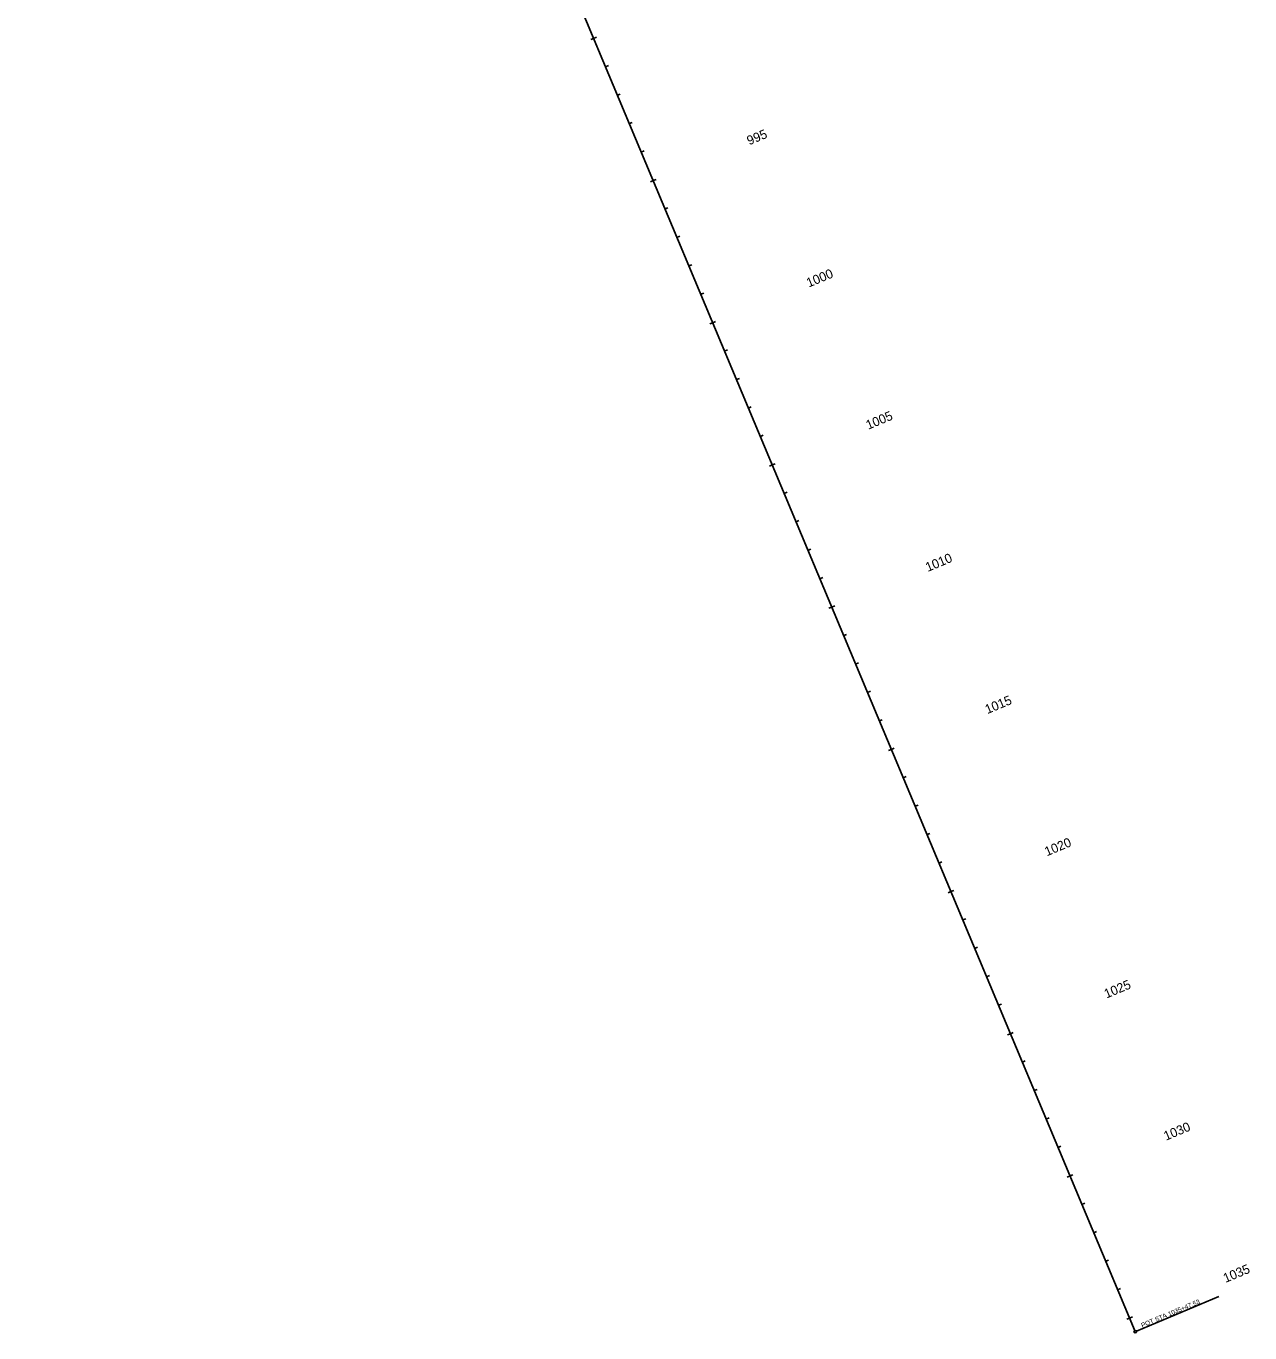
# Model space of a CAD drawing. Extents: x 2819977 to 2827606, y 116785 to 150320.
# Drawn here: x 2821726 to 2825694, y 116785 to 121023 of the extents above; entities that cross this region are included whole.
import ezdxf

# ---------------------------------------------------------------- set-up
doc = ezdxf.new("R2010")
doc.units = 0
doc.layers.add('Modeling-Flow Arrows-Existing', color=7, linetype='Continuous')
doc.layers.add('Modeling-Spot-Existing', color=7, linetype='Continuous')

msp = doc.modelspace()

# ---------------------------------------------------------------- linework, layer by layer
at = {"layer": 'Modeling-Flow Arrows-Existing'}
for p, q in [((2821725.8, 125379.3), (2825322, 116789)), ((2823565.9, 120983.8), (2823556.7, 120979.9)), ((2823565.9, 120983.8), (2823575.1, 120987.7)), ((2823604.5, 120891.6), (2823613.8, 120895.4)), ((2823643.1, 120799.3), (2823652.4, 120803.2)), ((2823681.8, 120707.1), (2823691, 120710.9)), ((2823720.4, 120614.8), (2823729.6, 120618.7)), ((2823759, 120522.6), (2823749.8, 120518.7)), ((2823759, 120522.6), (2823768.2, 120526.5)), ((2823797.6, 120430.4), (2823806.8, 120434.2)), ((2823836.2, 120338.1), (2823845.5, 120342)), ((2823874.8, 120245.9), (2823884.1, 120249.7)), ((2823913.5, 120153.6), (2823922.7, 120157.5)), ((2823952.1, 120061.4), (2823942.9, 120057.5)), ((2823952.1, 120061.4), (2823961.3, 120065.2)), ((2823990.7, 119969.1), (2823999.9, 119973)), ((2824029.3, 119876.9), (2824038.5, 119880.8)), ((2824067.9, 119784.7), (2824077.2, 119788.5)), ((2824106.5, 119692.4), (2824115.8, 119696.3)), ((2824145.2, 119600.2), (2824135.9, 119596.3)), ((2824145.2, 119600.2), (2824154.4, 119604)), ((2824183.8, 119507.9), (2824193, 119511.8)), ((2824222.4, 119415.7), (2824231.6, 119419.5)), ((2824261, 119323.4), (2824270.2, 119327.3)), ((2824299.6, 119231.2), (2824308.9, 119235.1)), ((2824338.3, 119139), (2824347.5, 119142.8)), ((2824338.3, 119139), (2824329, 119135.1)), ((2824376.9, 119046.7), (2824386.1, 119050.6)), ((2824415.5, 118954.5), (2824424.7, 118958.3)), ((2824454.1, 118862.2), (2824463.3, 118866.1)), ((2824492.7, 118770), (2824501.9, 118773.8)), ((2824531.3, 118677.7), (2824522.1, 118673.9)), ((2824531.3, 118677.7), (2824540.6, 118681.6)), ((2824570, 118585.5), (2824579.2, 118589.4)), ((2824608.6, 118493.3), (2824617.8, 118497.1)), ((2824647.2, 118401), (2824656.4, 118404.9)), ((2824685.8, 118308.8), (2824695, 118312.6)), ((2824724.4, 118216.5), (2824715.2, 118212.7)), ((2824724.4, 118216.5), (2824733.6, 118220.4)), ((2824763, 118124.3), (2824772.3, 118128.1)), ((2824801.7, 118032), (2824810.9, 118035.9)), ((2824840.3, 117939.8), (2824849.5, 117943.7)), ((2824878.9, 117847.6), (2824888.1, 117851.4)), ((2824917.5, 117755.3), (2824908.3, 117751.4)), ((2824917.5, 117755.3), (2824926.7, 117759.2)), ((2824956.1, 117663.1), (2824965.3, 117666.9)), ((2824994.7, 117570.8), (2825004, 117574.7)), ((2825033.4, 117478.6), (2825042.6, 117482.4)), ((2825072, 117386.3), (2825081.2, 117390.2)), ((2825110.6, 117294.1), (2825101.4, 117290.2)), ((2825110.6, 117294.1), (2825119.8, 117298)), ((2825149.2, 117201.9), (2825158.4, 117205.7)), ((2825187.8, 117109.6), (2825197, 117113.5)), ((2825226.4, 117017.4), (2825235.7, 117021.2)), ((2825265.1, 116925.1), (2825274.3, 116929)), ((2825303.7, 116832.9), (2825294.4, 116829)), ((2825303.7, 116832.9), (2825312.9, 116836.7))]:
    msp.add_line(p, q, dxfattribs=at)
at = {"layer": 'Modeling-Spot-Existing'}
msp.add_line((2825325.7, 116790.6), (2825593, 116902.5), dxfattribs=at)
msp.add_circle((2825322, 116789), 4, dxfattribs=at)

# ---------------------------------------------------------------- texts
at = {"layer": 'Modeling-Flow Arrows-Existing'}
for s, p in [(' 995', (2824060, 120632.3)), (' 1000', (2824253.1, 120171.1)), (' 1005', (2824446.1, 119709.9)), (' 1010', (2824639.2, 119248.7)), (' 1015', (2824832.3, 118787.5)), (' 1020', (2825025.4, 118326.3)), (' 1025', (2825218.5, 117865)), (' 1030', (2825411.6, 117403.8)), (' 1035', (2825604.6, 116942.6))]:
    msp.add_text(s, height=30, rotation=22.7163, dxfattribs=at).set_placement(p)
at = {"layer": 'Modeling-Spot-Existing'}
msp.add_text('POT STA 1035+47.53', height=15, rotation=22.7163, dxfattribs=at).set_placement((2825344.9, 116801.8))

doc.saveas('drawing.dxf')
